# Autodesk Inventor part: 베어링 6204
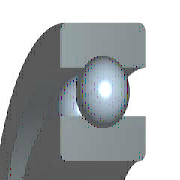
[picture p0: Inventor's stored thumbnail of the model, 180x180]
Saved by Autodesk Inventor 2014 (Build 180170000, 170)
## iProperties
IsCustomPart: 0
Created: 2018-09
Part Number: 베어링 6204
Material: 스테인리스강
Description: 깊은 그루브 볼 베어링
Document SubType Name: Modeling
Standard: KS B 2023
Standards Organization: KS
Language: ko-KR
Size Designation: 6204 - 20 x 47 x 14
Categories: <MemberInstance><Categories><Category DisplayName="샤프트 부품" InternalName="7f7aeb1f-a693-4053-b835-cee3144e0d98" Mnemonic="SHFT"><Category DisplayName="베어링" Inter
Density: 8.08 g/cm^3
Mass: 107.173 g
Surface Area: 87.8912 cm^2
Volume: 13.264 cm^3
Appearance: 노란색
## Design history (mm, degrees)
sketch "스케치" dims "d0" = 7.02 (= -0.26 x WD + 0.26 x BD)
  geometry: L1 (3.49, 16.75)-(10.51, 16.75); L2 (7, 16.75)-(7, 13.24); L3 (7, 16.75)-(7, 20.26); L4 (4.392, 14.401)-(0, 14.401); L5 (0, 10)-(14, 10); L6 (4.392, 19.099)-(0, 19.099); L7 (0, 23.5)-(14, 23.5); L8 (14, 10)-(14, 14.401); L9 (9.608, 14.401)-(14, 14.401); L10 (9.608, 19.099)-(14, 19.099); L11 (14, 23.5)-(14, 19.099); L12 (-1.4, 0)-(8.4, 0) reference; L13 (0, -0.3)-(0, 5.3) reference
  constraints: 22 end point, 4 point on line, 2 collinear, 2 perpendicular, 2 symmetric about line, 1 midpoint, 1 parallel, 14 other
  dimensions: "d9" = 20 diameter of L5 L12 (= WD); "d11" = 47 diameter of L7 L12 (= BD); "d12" = 14 distance between parallel lines of L8 L13 (= KB); "d13" = 28.802 diameter of L9 L12 (= 0.326 x BD + 0.674 x WD)
revolve "본체" stored, may be unused: angle "d6" = 90 deg
revolve "볼" stored, may be unused: angle "d7" = 90 deg
pattern_circular "IDS_ARRAYBALL[SIMPL:T]" dims angle "d3" = 360 deg
body "Solid1"
fillet "모깎기1" dims "d1" = 1 (= KRS)
other parameters: "WD" = 20 [user parameter; used in 5 equation terms], "BD" = 47 [user parameter; used in 5 equation terms], "KB" = 14 [user parameter; used in 1 equation term], "KRS" = 1 [user parameter; used in 1 equation term], "d4" = 0, "d5" = 0, "d8" = 0, "d14" = 0, "d15" = 0, "BBA" = 0 [user parameter], "BC0" = 6550000 [user parameter], "BC" = 1.27e+07 [user parameter], "BR" = 23.5 (= 0.5 x BD) [user parameter]
